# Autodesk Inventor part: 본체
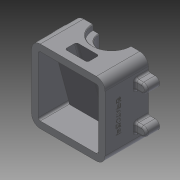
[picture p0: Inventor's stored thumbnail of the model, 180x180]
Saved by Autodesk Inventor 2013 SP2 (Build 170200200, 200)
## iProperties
Created: 2022-03
Part Number: 본체
Material: Generic
Document SubType Name: Modeling
Designer: a
Density: 1 g/cm^3
Author: a
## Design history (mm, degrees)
sketch "스케치1"
  geometry: L1 (-55, -55)-(55, -55); L2 (55, -55)-(55, 55); L3 (55, 55)-(-55, 55); L4 (-55, 55)-(-55, -55); L5 (-55, -55)-(55, 55); L6 (55, -55)-(-55, 55); 1 further point
  constraints: 12 end point, 2 midpoint, 2 parallel, 1 horizontal, 1 perpendicular
  dimensions: "d0" = 110 distance of L2.end L3.end; "d2" = 110 distance of L3.end L1.start
extrude "돌출1" new body sketch "스케치1" distance "d3" = 65; taper "d4" = 0 deg
sketch "스케치3"
  geometry: L1 (55, 55)-(-55, 55) reference; L2 (-55, 55)-(-55, -55) reference; L3 (-55, -55)-(55, -55) reference; L4 (55, -55)-(55, 55) reference; L5 (-45, -45)-(-45, 45); L6 (-45, 45)-(45, 45); L7 (45, 45)-(45, -45); L8 (45, -45)-(30, -45); L9 (30, -45)-(30, 33); L10 (30, 33)-(-30, 33); L11 (-30, 33)-(-30, -45); L12 (-30, -45)-(-45, -45); 2 further points
  constraints: 16 end point, 7 parallel, 1 midpoint, 1 perpendicular, 1 vertical alignment
  dimensions: "d16" = 10 distance between parallel lines of L4 L7; "d17" = 25 distance between parallel lines of L4 L9; "d18" = 25 distance between parallel lines of L2 L11; "d19" = 10 distance between parallel lines of L1 L6; "d20" = 10 distance between parallel lines of L3 L12; "d21" = 10 distance between parallel lines of L3 L8; "d23" = 22 distance between parallel lines of L1 L10
extrude "돌출2" cut sketch "스케치3" stored distance "d24" = 65; taper "d25" = 0 deg
fillet "모깎기1" dims "d26" = 13
sketch "스케치4"
  geometry: L1 (-55, 42)-(-55, -42) reference; L2 (42, 55)-(-42, 55) reference; L3 (-65, 35)-(-55, 35); L4 (-65, 21)-(-55, 21); L5 (-55, 35)-(-55, 21); L6 (-65, -21)-(-55, -21); L7 (-65, -35)-(-55, -35); L8 (-55, -21)-(-55, -35); A1 r 7 centre (-65, 28) between (-65, 35) and (-65, 21); A2 r 7 centre (-65, -28) between (-65, -21) and (-65, -35); 1 further point
  constraints: 12 end point, 4 point on circle, 4 point on line, 4 tangent, 2 centre point, 2 parallel, 2 perpendicular, 1 collinear
  dimensions: "d27" = 65 horizontal distance of point (0, 0) A1.centre; "d28" = 14 diameter of A1; "d29" = 27 distance from line of L2 A1.centre; "d30" = 14 diameter of A2; "d31" = 65 horizontal distance of point (0, 0) A2.centre; "d32" = 56 distance of A2.centre A1.centre
extrude "돌출3" join sketch "스케치4" distance "d33" = 20; taper "d34" = 0 deg
hole "구멍1" diameter "d37" = 3.242; stored, may be unused: countersink angle "d41" = 90 deg, drill point angle "d43" = 118 deg; dims "d35" = 10, "d36" = 10, "d38" = 9, "d39" = 4, "d40" = 2, "d42" = 11
hole "구멍2" diameter "d46" = 3.242; stored, may be unused: countersink angle "d50" = 90 deg, drill point angle "d52" = 118 deg; dims "d44" = 10, "d45" = 10, "d47" = 9, "d48" = 4, "d49" = 2, "d51" = 11
sketch "스케치7"
  geometry: L1 (37, 55)-(37, 47); L2 (37, 47)-(46, 47); L3 (46, 47)-(46, -25); L4 (46, -25)-(65, -25); L5 (37, 55)-(65, 55); L6 (65, -25)-(65, 55); 2 further points
  constraints: 12 end point, 2 perpendicular, 2 vertical, 1 parallel, 1 point on line
  dimensions: "d55" = 8 distance of L1.start L1.end; "d57" = 72 distance between parallel lines of L4 L2; "d60" = 38 diameter of L3 L6; "d61" = 56 diameter of L1 L6
revolve "회전1" sketch "스케치7" stored, may be unused: angle "d62" = 90 deg
sketch "스케치8" dims "d63" = 46
  geometry: A1 r 28 centre (0, 0) between (-28, 0) and (28, 0) reference; A2 r 19 centre (0, 0) between (-19, 0) and (19, 0) reference; 3 further points
  constraints: 2 vertical alignment, 1 coincident, 2 other
hole "구멍3" sketch "스케치8" at (0, -23) diameter "d64" = 3.242; stored, may be unused: countersink angle "d68" = 90 deg, drill point angle "d70" = 118 deg; dims "d65" = 9, "d66" = 4, "d67" = 2, "d69" = 11
sketch "스케치9"
  geometry: L1 (65, -19)-(65, 19); L2 (65, 19)-(38.843, 19); L3 (38.843, 19)-(29.197, 55); L4 (29.197, 55)-(11.597, 55); L5 (11.597, 55)-(31.425, -19); L6 (31.425, -19)-(65, -19); L7 (65, -25)-(65, 47) reference; L8 (37, 55)-(65, 55) reference; L9 (30, -33)-(7.833, 49.727); L10 (7.833, 49.727)-(0, 49.727); L11 (65, -33)-(0, -33) reference; L12 (30, -33)-(0, -33); L13 (0, -33)-(0, 49.727); L14 (0, -55)-(65, -55) reference; 2 further points
  constraints: 20 end point, 5 parallel, 3 point on line, 2 perpendicular, 1 collinear, 1 midpoint, 1 vertical
  dimensions: "d72" = 75 deg angle of L2 L3; "d73" = 17 distance between parallel lines of L5 L3; "d75" = 38 distance between parallel lines of L2 L6; "d77" = 36 distance between parallel lines of L8 L2; "d78" = 30 distance of L9.start L12.end; "d79" = 5 distance between parallel lines of L5 L9; "d80" = 22 distance between parallel lines of L14 L12; "d81" = 5.273 distance between parallel lines of L4 L10
extrude "돌출4" cut sketch "스케치9" stored distance "d82" = 34; taper "d83" = 0 deg
sketch "스케치10"
  geometry: C1 r 7.5 at (0, 0); A1 r 19 centre (0, 0) between (-19, 0) and (19, 0) reference; 1 further point
  constraints: 1 centre point, 1 coincident
  dimensions: "d84" = 15 diameter of C1
extrude "돌출5" cut sketch "스케치10" distance "d85" = 4; taper "d86" = -30 deg
sketch "스케치11"
  geometry: L1 (30, -33)-(9.1, 45); L2 (9.1, 45)-(0, 45); L3 (30, -33)-(0, -33); L4 (0, -33)-(0, 45); L5 (65, 55)-(0, 55) reference; L6 (11.597, 55)-(31.425, -19) reference; L7 (0, -55)-(65, -55) reference; 1 further point
  constraints: 8 end point, 2 parallel, 1 horizontal, 1 perpendicular, 1 point on line
  dimensions: "d87" = 10 distance between parallel lines of L5 L2; "d89" = 5 distance between parallel lines of L1 L6; "d90" = 22 distance between parallel lines of L7 L3
extrude "돌출6" cut sketch "스케치11" stored distance "d91" = 71.5; taper "d92" = 0 deg
fillet "모깎기2" dims "d93" = 3
fillet "모깎기4" dims "d95" = 3
fillet "모깎기7" dims "d98" = 3
fillet "모깎기10" dims "d101" = 3
fillet "모깎기11" dims "d102" = 3
fillet "모깎기12" dims "d103" = 3
fillet "모깎기13" dims "d104" = 3
fillet "모깎기14" dims "d105" = 1
chamfer "모따기2" distance "d109" = 1; stored, may be unused: second distance "d110" = 2, angle "d111" = 45 deg
sketch "스케치12"
  geometry: L1 (-13, 65)-(-13, 0) reference; 2 further points
  constraints: 1 other
  dimensions: "d112" = 55 distance from line of L1 point (42, 20); "d113" = 20 distance of point (42, 0) point (42, 20)
feature "엠보싱1" sketch "스케치12" dims "d0" = 110, "d2" = 110, "d16" = 10, "d17" = 25, "d18" = 25, "d19" = 10, "d20" = 10, "d21" = 10, "d23" = 22, "d114" = 0.5, "d115" = 0
fillet "모깎기20" dims "d121" = 3
fillet "모깎기21" dims "d122" = 3
node "솔리드1"
mirror "대칭1"
